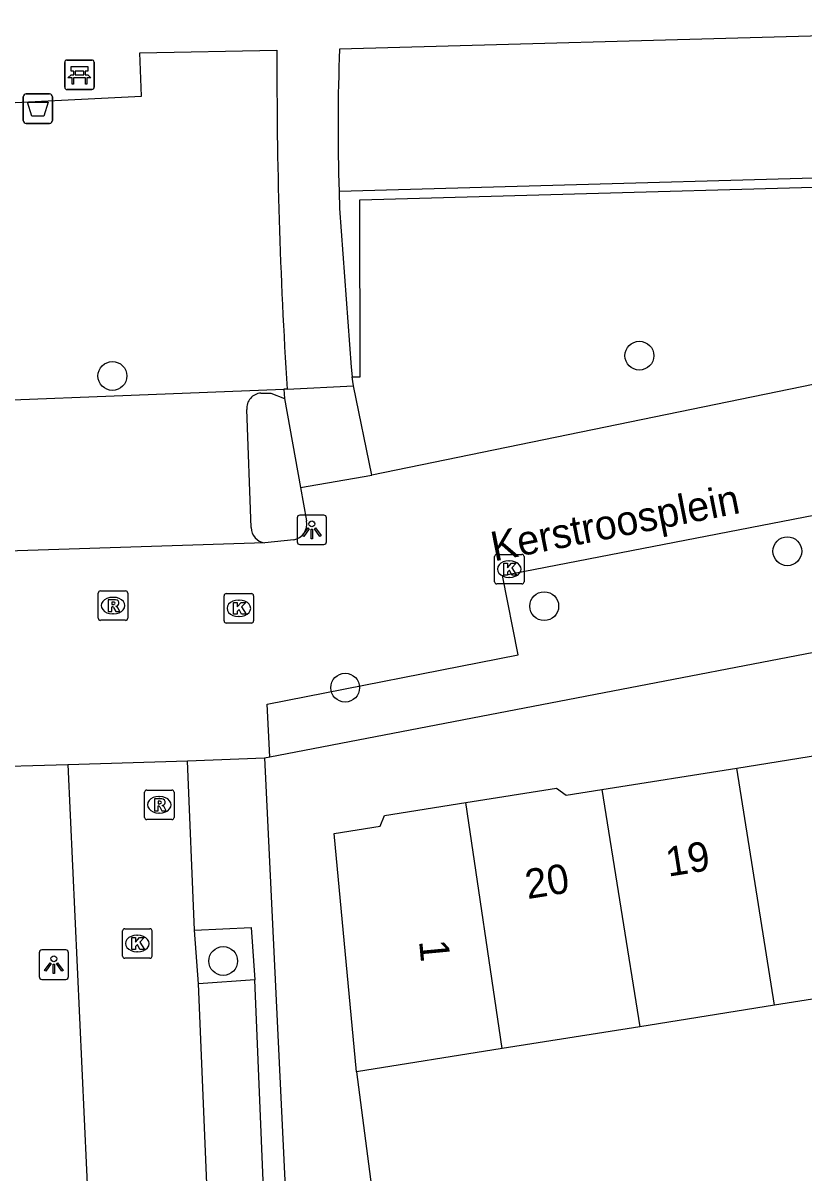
# Model space of a CAD drawing. Extents: x 162250 to 162654, y 380744 to 381605.
# Drawn here: x 162393.23 to 162419.71, y 381100.24 to 381139.25 of the extents above; entities that cross this region are included whole.
import ezdxf

# ---------------------------------------------------------------- set-up
doc = ezdxf.new("R2010")
doc.units = 0
for name, color, linetype in [('IMGEO_Afvalbak', 7, 'Continuous'), ('IMGEO_Bank', 7, 'Continuous'), ('IMGEO_Boom', 7, 'Continuous'), ('IMGEO_Haag', 7, 'Continuous'), ('IMGEO_Kolk', 7, 'Continuous'), ('IMGEO_Lichtpunt', 7, 'Continuous'), ('IMGEO_Muur', 7, 'Continuous'), ('IMGEO_Openbare_ruimte_label', 7, 'Continuous'), ('IMGEO_Pand', 7, 'Continuous'), ('IMGEO_Pand_nummerreeks', 7, 'Continuous'), ('IMGEO_Parkeervlak_open', 7, 'Continuous'), ('IMGEO_Rijbaan_lokaal_open', 7, 'Continuous'), ('IMGEO_Rioolput', 7, 'Continuous'), ('IMGEO_Voetpad_gesloten', 7, 'Continuous'), ('IMGEO_Voetpad_open', 7, 'Continuous'), ('IMGEO_Woonerf_open', 7, 'Continuous')]:
    doc.layers.add(name, color=color, linetype=linetype)

msp = doc.modelspace()

# ---------------------------------------------------------------- linework, layer by layer
at = {"layer": 'IMGEO_Afvalbak'}
for p, q in [((162393.34, 381136.844), (162394.13, 381136.844)), ((162394.13, 381136.844), (162393.34, 381136.844)), ((162393.24, 381135.944), (162393.24, 381136.744)), ((162393.24, 381136.744), (162393.24, 381135.944)), ((162394.23, 381136.744), (162394.23, 381135.944)), ((162394.23, 381135.944), (162394.23, 381136.744)), ((162394.13, 381135.844), (162393.34, 381135.844)), ((162393.34, 381135.844), (162394.13, 381135.844))]:
    msp.add_line(p, q, dxfattribs=at)
msp.add_lwpolyline([(162393.383, 381136.558), (162394.087, 381136.558), (162393.938, 381136.088), (162393.532, 381136.088), (162393.383, 381136.558)], dxfattribs=at)
for centre, start, end in [((162393.34, 381136.744), 90, 180), ((162393.34, 381136.744), 90, 180), ((162394.13, 381136.744), 0, 90), ((162394.13, 381136.744), 360, 90), ((162393.34, 381135.944), 180, 270), ((162393.34, 381135.944), 180, 270), ((162394.13, 381135.944), 270, 0), ((162394.13, 381135.944), 270, 0)]:
    msp.add_arc(centre, 0.1, start, end, dxfattribs=at)
at = {"layer": 'IMGEO_Bank'}
for p, q in [((162394.718, 381137.991), (162395.559, 381137.991)), ((162395.559, 381137.991), (162394.718, 381137.991)), ((162394.643, 381137.066), (162394.643, 381137.907)), ((162394.643, 381137.907), (162394.643, 381137.066)), ((162394.952, 381137.497), (162394.952, 381137.603)), ((162394.996, 381137.603), (162394.996, 381137.497)), ((162395.284, 381137.609), (162395.002, 381137.609)), ((162395.29, 381137.497), (162395.29, 381137.603)), ((162395.334, 381137.603), (162395.334, 381137.497)), ((162395.643, 381137.916), (162395.643, 381137.075)), ((162395.643, 381137.075), (162395.643, 381137.916)), ((162395.34, 381137.389), (162394.947, 381137.389)), ((162395.002, 381137.491), (162395.284, 381137.491)), ((162395.568, 381136.991), (162394.727, 381136.991)), ((162394.727, 381136.991), (162395.568, 381136.991))]:
    msp.add_line(p, q, dxfattribs=at)
for points in [[(162394.946, 381137.609), (162394.86, 381137.609), (162394.86, 381137.77), (162395.423, 381137.77), (162395.423, 381137.609), (162395.34, 381137.609)], [(162394.89, 381137.389), (162394.748, 381137.389), (162394.86, 381137.491), (162394.946, 381137.491)], [(162394.94, 381137.382), (162394.94, 381137.175), (162394.897, 381137.175), (162394.897, 381137.382)], [(162395.34, 381137.491), (162395.423, 381137.491), (162395.535, 381137.389), (162395.396, 381137.389)], [(162395.39, 381137.382), (162395.39, 381137.175), (162395.346, 381137.175), (162395.346, 381137.382)]]:
    msp.add_lwpolyline(points, dxfattribs=at)
for centre, radius, start, end in [((162394.721, 381137.913), 0.0779, 92.4484, 184.2845), ((162394.721, 381137.913), 0.0779, 92.4484, 184.2845), ((162395.565, 381137.913), 0.0779, 2.4484, 94.2845), ((162395.565, 381137.913), 0.0779, 2.4484, 94.2845), ((162394.945, 381137.602), 0.00671, 2.8957, 87.1043), ((162395.002, 381137.602), 0.00671, 92.8957, 177.1043), ((162395.284, 381137.602), 0.00671, 2.8957, 87.1043), ((162395.341, 381137.602), 0.00671, 92.8957, 177.1043), ((162394.89, 381137.382), 0.00671, 2.8957, 87.1043), ((162394.947, 381137.382), 0.00671, 92.8957, 177.1043), ((162394.945, 381137.498), 0.00671, 272.8957, 357.1043), ((162395.002, 381137.498), 0.00671, 182.8957, 267.1043), ((162395.284, 381137.498), 0.00671, 272.8957, 357.1043), ((162395.341, 381137.498), 0.00671, 182.8957, 267.1043), ((162395.339, 381137.382), 0.00671, 2.8957, 87.1043), ((162395.396, 381137.382), 0.00671, 92.8957, 177.1043), ((162394.721, 381137.069), 0.0779, 182.4484, 274.2845), ((162394.721, 381137.069), 0.0779, 182.4484, 274.2845), ((162395.565, 381137.069), 0.0779, 272.4484, 4.2845), ((162395.565, 381137.069), 0.0779, 272.4484, 4.2845)]:
    msp.add_arc(centre, radius, start, end, dxfattribs=at)
at = {"layer": 'IMGEO_Boom'}
for centre in [(162414.132, 381127.963), (162396.262, 381127.276), (162419.148, 381121.33), (162410.905, 381119.467), (162404.155, 381116.702), (162400.019, 381107.43)]:
    msp.add_circle(centre, 0.489, dxfattribs=at)
at = {"layer": 'IMGEO_Haag'}
for points in [[(162426.769, 381139.248), (162427.289, 381134.188), (162403.947, 381133.536)], [(162404.397, 381127.245), (162404.661, 381127.245), (162404.653, 381133.255), (162427.32, 381133.888), (162428.391, 381128.701)]]:
    msp.add_lwpolyline(points, dxfattribs=at)
at = {"layer": 'IMGEO_Kolk'}
for p, q in [((162409.294, 381121.224), (162410.146, 381121.224)), ((162409.219, 381120.298), (162409.219, 381121.15)), ((162409.707, 381121.004), (162409.732, 381121.004)), ((162410.22, 381121.15), (162410.22, 381120.298)), ((162409.73, 381120.444), (162409.705, 381120.444)), ((162410.146, 381120.224), (162409.294, 381120.224)), ((162400.049, 381118.968), (162400.049, 381119.82)), ((162400.124, 381119.894), (162400.976, 381119.894)), ((162400.537, 381119.674), (162400.562, 381119.674)), ((162401.05, 381119.82), (162401.05, 381118.968)), ((162400.976, 381118.894), (162400.124, 381118.894)), ((162400.56, 381119.114), (162400.535, 381119.114)), ((162396.603, 381107.598), (162396.603, 381108.45)), ((162396.678, 381108.524), (162397.53, 381108.524)), ((162397.091, 381108.304), (162397.116, 381108.304)), ((162397.604, 381108.45), (162397.604, 381107.598)), ((162397.53, 381107.524), (162396.678, 381107.524)), ((162397.114, 381107.744), (162397.089, 381107.744))]:
    msp.add_line(p, q, dxfattribs=at)
for points in [[(162409.294, 381121.224), (162410.146, 381121.224)], [(162409.219, 381120.298), (162409.219, 381121.15)], [(162409.54, 381120.924), (162409.663, 381120.924), (162409.663, 381120.773), (162409.793, 381120.924), (162409.957, 381120.924), (162409.811, 381120.773), (162409.964, 381120.524), (162409.812, 381120.524), (162409.727, 381120.688), (162409.663, 381120.621), (162409.663, 381120.524), (162409.54, 381120.524), (162409.54, 381120.924)], [(162410.22, 381121.15), (162410.22, 381120.298)], [(162410.146, 381120.224), (162409.294, 381120.224)], [(162400.049, 381118.968), (162400.049, 381119.82)], [(162400.124, 381119.894), (162400.976, 381119.894)], [(162401.05, 381119.82), (162401.05, 381118.968)], [(162400.37, 381119.594), (162400.493, 381119.594), (162400.493, 381119.443), (162400.623, 381119.594), (162400.787, 381119.594), (162400.641, 381119.443), (162400.794, 381119.194), (162400.642, 381119.194), (162400.557, 381119.358), (162400.493, 381119.291), (162400.493, 381119.194), (162400.37, 381119.194), (162400.37, 381119.594)], [(162400.976, 381118.894), (162400.124, 381118.894)], [(162396.603, 381107.598), (162396.603, 381108.45)], [(162396.678, 381108.524), (162397.53, 381108.524)], [(162397.604, 381108.45), (162397.604, 381107.598)], [(162396.924, 381108.224), (162397.047, 381108.224), (162397.047, 381108.073), (162397.177, 381108.224), (162397.341, 381108.224), (162397.195, 381108.073), (162397.348, 381107.824), (162397.196, 381107.824), (162397.111, 381107.988), (162397.047, 381107.921), (162397.047, 381107.824), (162396.924, 381107.824), (162396.924, 381108.224)], [(162397.53, 381107.524), (162396.678, 381107.524)]]:
    msp.add_lwpolyline(points, dxfattribs=at)
for centre, start, end in [((162409.296, 381121.148), 91.552, 178.448), ((162409.296, 381121.148), 91.552, 178.448), ((162410.144, 381121.148), 1.552, 88.448), ((162410.144, 381121.148), 1.552, 88.448), ((162409.296, 381120.3), 181.552, 268.448), ((162409.296, 381120.3), 181.552, 268.448), ((162410.144, 381120.3), 271.552, 358.448), ((162410.144, 381120.3), 271.552, 358.448), ((162400.126, 381119.818), 91.552, 178.448), ((162400.126, 381119.818), 91.552, 178.448), ((162400.974, 381119.818), 1.552, 88.448), ((162400.974, 381119.818), 1.552, 88.448), ((162400.126, 381118.97), 181.552, 268.448), ((162400.126, 381118.97), 181.552, 268.448), ((162400.974, 381118.97), 271.552, 358.448), ((162400.974, 381118.97), 271.552, 358.448), ((162396.68, 381108.448), 91.552, 178.448), ((162396.68, 381108.448), 91.552, 178.448), ((162397.528, 381108.448), 1.552, 88.448), ((162397.528, 381108.448), 1.552, 88.448), ((162396.68, 381107.6), 181.552, 268.448), ((162396.68, 381107.6), 181.552, 268.448), ((162397.528, 381107.6), 271.552, 358.448), ((162397.528, 381107.6), 271.552, 358.448)]:
    msp.add_arc(centre, 0.0765, start, end, dxfattribs=at)
for centre, major_axis, ratio, start_param, end_param in [((162409.706, 381120.724), (-0.387, 0.002), 0.722429, 4.712389, 7.853982), ((162409.731, 381120.724), (-0.39, 0.002), 0.717154, 1.570796, 4.712389), ((162400.536, 381119.394), (-0.387, 0.002), 0.722429, 4.712389, 7.853982), ((162400.561, 381119.394), (-0.39, 0.002), 0.717154, 1.570796, 4.712389), ((162397.09, 381108.024), (-0.387, 0.002), 0.722429, 4.712389, 7.853982), ((162397.115, 381108.024), (-0.39, 0.002), 0.717154, 1.570796, 4.712389)]:
    msp.add_ellipse(centre, major_axis=major_axis, ratio=ratio, start_param=start_param, end_param=end_param, dxfattribs=at)
at = {"layer": 'IMGEO_Lichtpunt'}
for p, q in [((162402.526, 381122.459), (162402.526, 381121.652)), ((162402.526, 381122.459), (162402.526, 381121.652)), ((162403.428, 381122.554), (162402.62, 381122.554)), ((162403.428, 381122.554), (162402.62, 381122.554)), ((162403.522, 381121.652), (162403.522, 381122.459)), ((162403.522, 381121.652), (162403.522, 381122.459)), ((162402.62, 381121.558), (162403.428, 381121.558)), ((162402.62, 381121.558), (162403.428, 381121.558)), ((162393.777, 381107.71), (162393.777, 381106.903)), ((162393.777, 381107.71), (162393.777, 381106.903)), ((162394.679, 381107.805), (162393.871, 381107.805)), ((162394.679, 381107.805), (162393.871, 381107.805)), ((162394.773, 381106.903), (162394.773, 381107.71)), ((162394.773, 381106.903), (162394.773, 381107.71)), ((162393.871, 381106.809), (162394.679, 381106.809)), ((162393.871, 381106.809), (162394.679, 381106.809))]:
    msp.add_line(p, q, dxfattribs=at)
for points in [[(162402.9, 381122.123), (162402.939, 381122.095), (162402.751, 381121.833), (162402.713, 381121.86), (162402.9, 381122.123)], [(162403.002, 381122.075), (162403.049, 381122.075), (162403.049, 381121.753), (162403.002, 381121.753), (162403.002, 381122.075)], [(162403.112, 381122.095), (162403.15, 381122.122), (162403.337, 381121.86), (162403.298, 381121.832), (162403.112, 381122.095)], [(162394.151, 381107.374), (162394.19, 381107.346), (162394.002, 381107.084), (162393.964, 381107.111), (162394.151, 381107.374)], [(162394.253, 381107.326), (162394.3, 381107.326), (162394.3, 381107.004), (162394.253, 381107.004), (162394.253, 381107.326)], [(162394.363, 381107.346), (162394.401, 381107.373), (162394.588, 381107.111), (162394.549, 381107.083), (162394.363, 381107.346)]]:
    msp.add_lwpolyline(points, dxfattribs=at)
for centre in [(162403.025, 381122.257), (162394.276, 381107.508)]:
    msp.add_circle(centre, 0.0994, dxfattribs=at)
for centre, start, end in [((162402.62, 381122.459), 90, 180), ((162402.62, 381122.459), 90, 180), ((162403.428, 381122.459), 0, 90), ((162403.428, 381122.459), 0, 90), ((162402.62, 381121.652), 180, 270), ((162402.62, 381121.652), 180, 270), ((162403.428, 381121.652), 270, 0), ((162403.428, 381121.652), 270, 360), ((162393.871, 381107.71), 90, 180), ((162393.871, 381107.71), 90, 180), ((162394.679, 381107.71), 0, 90), ((162394.679, 381107.71), 0, 90), ((162393.871, 381106.903), 180, 270), ((162393.871, 381106.903), 180, 270), ((162394.679, 381106.903), 270, 0), ((162394.679, 381106.903), 270, 360)]:
    msp.add_arc(centre, 0.0946, start, end, dxfattribs=at)
at = {"layer": 'IMGEO_Muur'}
msp.add_lwpolyline([(162404.544, 381103.674), (162405.189, 381098.733)], dxfattribs=at)
at = {"layer": 'IMGEO_Pand'}
for points in [[(162417.432, 381113.976), (162422.345, 381114.763)], [(162412.864, 381113.25), (162417.432, 381113.976)], [(162418.713, 381105.929), (162417.432, 381113.976)], [(162408.251, 381112.81), (162411.318, 381113.297), (162411.649, 381113.057), (162412.864, 381113.25)], [(162412.864, 381113.25), (162414.145, 381105.202)], [(162409.483, 381104.458), (162404.544, 381103.674), (162403.787, 381111.757), (162405.342, 381112.003), (162405.483, 381112.371), (162408.251, 381112.81)], [(162409.483, 381104.458), (162408.251, 381112.81)], [(162422.941, 381106.596), (162418.713, 381105.929)], [(162418.713, 381105.929), (162414.145, 381105.202)], [(162414.145, 381105.202), (162409.483, 381104.458)]]:
    msp.add_lwpolyline(points, dxfattribs=at)
at = {"layer": 'IMGEO_Parkeervlak_open'}
for points in [[(162387.106, 381126.653), (162387.113, 381126.237), (162402.073, 381126.826)], [(162401.298, 381126.692), (162401.637, 381126.694), (162402.093, 381126.509)], [(162400.966, 381122.131), (162400.817, 381126.136)], [(162401.426, 381121.617), (162386.393, 381121.126)], [(162401.091, 381106.793), (162399.178, 381106.658)]]:
    msp.add_lwpolyline(points, dxfattribs=at)
for centre, radius, start, end in [((162401.334, 381126.175), 0.519, 94.0001, 184.2732), ((162401.483, 381122.131), 0.517, 180.0235, 263.6299)]:
    msp.add_arc(centre, radius, start, end, dxfattribs=at)
at = {"layer": 'IMGEO_Rijbaan_lokaal_open'}
for points in [[(162394.749, 381114.092), (162398.809, 381114.226)], [(162399.043, 381108.473), (162398.809, 381114.226)], [(162394.749, 381114.092), (162395.702, 381093.475)], [(162399.178, 381106.658), (162399.043, 381108.473)], [(162399.638, 381095.809), (162399.178, 381106.658)]]:
    msp.add_lwpolyline(points, dxfattribs=at)
at = {"layer": 'IMGEO_Rioolput'}
for p, q in [((162395.783, 381119.061), (162395.783, 381119.913)), ((162395.858, 381119.987), (162396.71, 381119.987)), ((162396.271, 381119.767), (162396.296, 381119.767)), ((162396.784, 381119.913), (162396.784, 381119.061)), ((162396.71, 381118.987), (162395.858, 381118.987)), ((162396.294, 381119.207), (162396.269, 381119.207)), ((162397.352, 381112.304), (162397.352, 381113.156)), ((162397.427, 381113.23), (162398.279, 381113.23)), ((162397.84, 381113.01), (162397.865, 381113.01)), ((162398.353, 381113.156), (162398.353, 381112.304)), ((162398.279, 381112.23), (162397.427, 381112.23)), ((162397.863, 381112.45), (162397.838, 381112.45))]:
    msp.add_line(p, q, dxfattribs=at)
for points in [[(162395.783, 381119.061), (162395.783, 381119.913)], [(162395.858, 381119.987), (162396.71, 381119.987)], [(162396.372, 381119.685), (162396.12, 381119.687), (162396.12, 381119.287)], [(162396.298, 381119.606), (162396.244, 381119.606), (162396.244, 381119.525)], [(162396.784, 381119.913), (162396.784, 381119.061)], [(162396.12, 381119.287), (162396.244, 381119.287), (162396.244, 381119.449), (162396.255, 381119.449)], [(162396.244, 381119.525), (162396.296, 381119.525)], [(162396.302, 381119.42), (162396.373, 381119.287), (162396.513, 381119.287), (162396.448, 381119.413)], [(162396.71, 381118.987), (162395.858, 381118.987)], [(162397.352, 381112.304), (162397.352, 381113.156)], [(162397.427, 381113.23), (162398.279, 381113.23)], [(162398.353, 381113.156), (162398.353, 381112.304)], [(162397.941, 381112.928), (162397.689, 381112.93), (162397.689, 381112.53)], [(162397.689, 381112.53), (162397.813, 381112.53), (162397.813, 381112.692), (162397.824, 381112.692)], [(162397.867, 381112.849), (162397.813, 381112.849), (162397.813, 381112.768)], [(162397.813, 381112.768), (162397.865, 381112.768)], [(162397.871, 381112.663), (162397.942, 381112.53), (162398.082, 381112.53), (162398.017, 381112.656)], [(162398.279, 381112.23), (162397.427, 381112.23)]]:
    msp.add_lwpolyline(points, dxfattribs=at)
for centre, radius, start, end in [((162395.86, 381119.911), 0.0765, 91.552, 178.448), ((162395.86, 381119.911), 0.0765, 91.552, 178.448), ((162396.304, 381119.51), 0.0964, 77.0061, 93.1865), ((162396.371, 381119.575), 0.109, 350.3612, 89.416), ((162396.708, 381119.911), 0.0765, 1.552, 88.448), ((162396.708, 381119.911), 0.0765, 1.552, 88.448), ((162396.254, 381119.396), 0.0533, 26.0293, 88.6989), ((162396.28, 381119.714), 0.19, 274.7715, 282.9687), ((162396.318, 381119.567), 0.0378, 276.6634, 79.6772), ((162396.369, 381119.575), 0.112, 277.5842, 350.9817), ((162396.353, 381119.36), 0.108, 29.5134, 73.7905), ((162395.86, 381119.063), 0.0765, 181.552, 268.448), ((162395.86, 381119.063), 0.0765, 181.552, 268.448), ((162396.708, 381119.063), 0.0765, 271.552, 358.448), ((162396.708, 381119.063), 0.0765, 271.552, 358.448), ((162397.429, 381113.154), 0.0765, 91.552, 178.448), ((162397.429, 381113.154), 0.0765, 91.552, 178.448), ((162398.277, 381113.154), 0.0765, 1.552, 88.448), ((162398.277, 381113.154), 0.0765, 1.552, 88.448), ((162397.823, 381112.639), 0.0533, 26.0293, 88.6989), ((162397.849, 381112.957), 0.19, 274.7715, 282.9687), ((162397.873, 381112.753), 0.0964, 77.0061, 93.1865), ((162397.887, 381112.81), 0.0378, 276.6634, 79.6772), ((162397.94, 381112.818), 0.109, 350.3612, 89.416), ((162397.938, 381112.818), 0.112, 277.5842, 350.9817), ((162397.922, 381112.603), 0.108, 29.5134, 73.7905), ((162397.429, 381112.306), 0.0765, 181.552, 268.448), ((162397.429, 381112.306), 0.0765, 181.552, 268.448), ((162398.277, 381112.306), 0.0765, 271.552, 358.448), ((162398.277, 381112.306), 0.0765, 271.552, 358.448)]:
    msp.add_arc(centre, radius, start, end, dxfattribs=at)
for centre, major_axis, ratio, start_param, end_param in [((162396.27, 381119.487), (-0.387, 0.002), 0.722429, 4.712389, 7.853982), ((162396.295, 381119.487), (-0.39, 0.002), 0.717154, 1.570796, 4.712389), ((162397.839, 381112.73), (-0.387, 0.002), 0.722429, 4.712389, 7.853982), ((162397.864, 381112.73), (-0.39, 0.002), 0.717154, 1.570796, 4.712389)]:
    msp.add_ellipse(centre, major_axis=major_axis, ratio=ratio, start_param=start_param, end_param=end_param, dxfattribs=at)
at = {"layer": 'IMGEO_Voetpad_gesloten'}
for points in [[(162426.769, 381139.248), (162426.519, 381139.246), (162426.569, 381137.73), (162420.451, 381137.624), (162420.336, 381138.812), (162403.962, 381138.361)], [(162387.564, 381137.904), (162390.166, 381137.88), (162390.243, 381136.417), (162397.246, 381136.763), (162397.189, 381138.232), (162401.842, 381138.323)], [(162403.947, 381133.536), (162403.966, 381132.96), (162404.361, 381127.574), (162404.397, 381127.245)], [(162404.433, 381126.937), (162404.415, 381127.091), (162404.397, 381127.245)], [(162402.189, 381126.831), (162404.433, 381126.937)]]:
    msp.add_lwpolyline(points, dxfattribs=at)
for centre, radius, start, end in [((162477.611, 381135.72), 73.697, 177.94592, 181.69783), ((162567.878, 381137.585), 166.038, 179.7454, 183.71363)]:
    msp.add_arc(centre, radius, start, end, dxfattribs=at)
at = {"layer": 'IMGEO_Voetpad_open'}
for points in [[(162402.189, 381126.831), (162402.073, 381126.826)], [(162402.073, 381126.826), (162402.093, 381126.509)], [(162405.054, 381123.907), (162404.433, 381126.937)], [(162402.093, 381126.509), (162402.641, 381123.487)], [(162401.595, 381114.357), (162401.509, 381116.144), (162410.022, 381117.819), (162409.493, 381120.503), (162425.183, 381123.553), (162425.704, 381120.904), (162439.872, 381123.692), (162443.007, 381124.274)], [(162402.641, 381123.487), (162405.054, 381123.907)], [(162401.595, 381114.357), (162431.678, 381120.144), (162440.223, 381121.823), (162443.348, 381122.437)], [(162398.809, 381114.226), (162401.417, 381114.323)], [(162401.417, 381114.323), (162402.29, 381096.222)], [(162391.565, 381114.004), (162394.749, 381114.098), (162394.749, 381114.092)], [(162399.043, 381108.473), (162400.964, 381108.569), (162401.091, 381106.793)], [(162399.638, 381095.809), (162401.545, 381095.89), (162401.091, 381106.793)]]:
    msp.add_lwpolyline(points, dxfattribs=at)
at = {"layer": 'IMGEO_Woonerf_open'}
for points in [[(162428.391, 381128.701), (162405.054, 381123.907)], [(162402.641, 381123.487), (162402.846, 381122.358)], [(162402.409, 381121.718), (162401.426, 381121.617)], [(162401.417, 381114.323), (162401.595, 381114.357)]]:
    msp.add_lwpolyline(points, dxfattribs=at)
msp.add_arc((162402.307, 381122.257), 0.549, 280.7563, 10.5922, dxfattribs=at)

# ---------------------------------------------------------------- texts
at = {"layer": 'IMGEO_Openbare_ruimte_label'}
msp.add_text('Kerstroosplein', height=1, rotation=11.1301, dxfattribs=at).set_placement((162409.206, 381120.984))
at = {"layer": 'IMGEO_Pand_nummerreeks'}
for s, rotation, p in [('19', 9.0526, (162415.11, 381110.289)), ('20', 9.0526, (162410.34, 381109.529)), ('1', 275.3503, (162406.66, 381108.111))]:
    msp.add_text(s, height=1, rotation=rotation, dxfattribs=at).set_placement(p)

doc.saveas('drawing.dxf')
